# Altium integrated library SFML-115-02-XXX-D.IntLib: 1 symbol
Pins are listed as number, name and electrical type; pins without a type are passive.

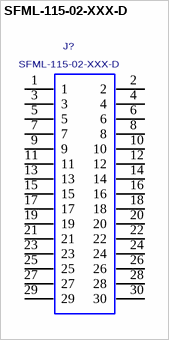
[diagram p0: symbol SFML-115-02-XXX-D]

## SFML-115-02-XXX-D
designator J?
Locking Socket Assembly, Surface Mount, Dual Row, 0.050" x 0.050", 30 Pins,; MANUFACTURER: SAMTEC
footprint SFML-115-02-XXX-D
pins: 1, 2, 3, 4, 5, 6, 7, 8, 9, 10, 11, 12, 13, 14, 15, 16, 17, 18, 19, 20, 21, 22, 23, 24, 25, 26, 27, 28, 29, 30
